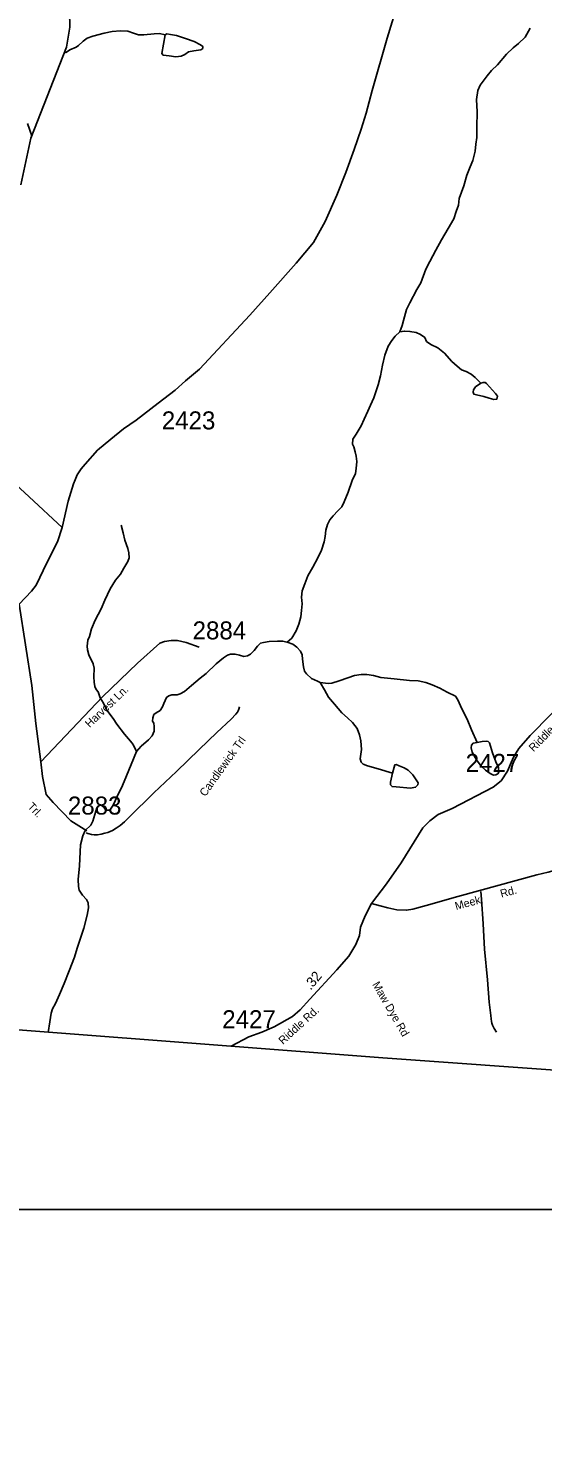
# Model space of a CAD drawing. Extents: x 1268485 to 1426702, y 514839 to 616766.
# Drawn here: x 1353261 to 1357479, y 515585 to 527189 of the extents above; entities that cross this region are included whole.
import ezdxf

# ---------------------------------------------------------------- set-up
doc = ezdxf.new("R2010")
doc.units = 0
for name, color, linetype in [('Old_Level_10', 7, 'Continuous'), ('Old_Level_11', 7, 'Continuous'), ('Old_Level_17', 7, 'Continuous'), ('Old_Level_32', 7, 'Continuous'), ('Old_Level_35', 7, 'Continuous'), ('Old_Level_52', 7, 'Continuous'), ('Old_Level_59', 7, 'Continuous'), ('Old_Level_62', 7, 'Continuous'), ('Old_Level_63', 7, 'Continuous'), ('Old_Level_8', 7, 'Continuous')]:
    doc.layers.add(name, color=color, linetype=linetype)

msp = doc.modelspace()

# ---------------------------------------------------------------- linework, layer by layer
at = {"layer": 'Old_Level_32'}
for points in [[(1356274.314, 527339.472), (1356204.23, 527108.832), (1356081.106, 526678.797), (1356031.384, 526491.805), (1355991.606, 526362.243), (1355934.307, 526193.629), (1355864.222, 526005.258), (1355791.296, 525820.563), (1355696.586, 525604.627), (1355600.455, 525433.257), (1355458.391, 525264.183), (1355242.453, 525019.761), (1355077.659, 524837.823), (1354665.299, 524394.975), (1354551.123, 524299.427), (1354465.311, 524221.316), (1354326.896, 524114.449), (1354145.716, 523974.995), (1354040.114, 523905.619), (1353937.828, 523821.082), (1353827.965, 523729.194), (1353727.099, 523615.713), (1353694.898, 523577.12), (1353661.749, 523528.419), (1353645.649, 523487.07), (1353630.495, 523453.99), (1353588.803, 523312.114), (1353537.161, 523096.675)], [(1353537.161, 523096.675), (1353266.596, 523346.181), (1352892.233, 523690.602), (1352735.016, 523837.622)], [(1353537.161, 523096.675), (1353500.054, 522977.251), (1353413.978, 522807.132), (1353324.923, 522623.315), (1353287.817, 522575.04), (1353184.651, 522468.203)], [(1353184.651, 522468.203), (1353289.673, 521801.897), (1353321.213, 521489.966), (1353363.462, 521174.024)], [(1353363.462, 521174.024), (1353869.457, 521708.317), (1354157.031, 521983.113), (1354340.706, 522146.506), (1354377.813, 522161.36), (1354431.617, 522168.786), (1354483.565, 522170.643), (1354554.067, 522153.933), (1354661.675, 522114.941)], [(1358031.866, 522051.038), (1357906.61, 521921.461), (1357804.568, 521817.484), (1357715.513, 521735.787), (1357377.847, 521390.435), (1357283.226, 521284.601), (1357238.698, 521212.189), (1357220.145, 521169.484), (1357191.799, 521097.247), (1357138.763, 521018.224), (1357072.466, 520966.767), (1356736.249, 520793.099), (1356622.597, 520743.48), (1356554.407, 520690.185), (1356497.582, 520633.215), (1356318.581, 520347.445), (1356197.354, 520174.697), (1356076.128, 520012.984)], [(1353363.462, 521174.024), (1353376.872, 521054.377), (1353408.412, 520905.838), (1353464.64, 520841.132), (1353608.786, 520691.2), (1353740.513, 520609.504)], [(1356076.128, 520012.984), (1356146.212, 519994.607), (1356209.667, 519978.986), (1356283.215, 519960.383), (1356362.993, 519958.527), (1356414.942, 519967.81), (1356524.101, 519997.364), (1356783.603, 520070.873), (1357431.412, 520247.297), (1357524.227, 520271.187), (1357584.84, 520285.889), (1357620.893, 520289.021), (1357672.841, 520279.737), (1357694.703, 520269.35), (1357880.999, 520210.952), (1358175.63, 520142.339), (1358218.443, 520123.248), (1358294.211, 520080.981), (1358392.708, 520018.497), (1358745.971, 519782.347)], [(1356076.128, 520012.984), (1356023.091, 519911.908), (1355985.207, 519818.182), (1355977.857, 519750.186), (1355947.63, 519677.802), (1355890.631, 519583.044), (1355792.177, 519470.772), (1355570.379, 519228.093), (1355489.475, 519141.881), (1355427.295, 519087.321), (1355276.591, 519003.549), (1355177.274, 518959.611), (1355070.598, 518919.777), (1354923.757, 518842.565)]]:
    msp.add_lwpolyline(points, dxfattribs=at)
at = {"layer": 'Old_Level_35'}
for points in [[(1353736.339, 520593.878), (1353748.421, 520588.178), (1353759.801, 520584.231), (1353779.589, 520579.565), (1353802.144, 520576.9), (1353827.981, 520577.567), (1353857.201, 520581.565), (1353887.139, 520588.844), (1353913.59, 520596.79), (1353950.705, 520612.733), (1353981.975, 520630.008), (1354013.861, 520651.898), (1354049.642, 520682.399), (1354082.861, 520716.233), (1354147.862, 520781.286), (1354230.088, 520860.231), (1354291.296, 520919.952), (1354476.971, 521096.502), (1354662.851, 521276.332), (1354808.13, 521414.333), (1354923.574, 521525.163), (1354962.124, 521564.995), (1354975.35, 521580.886), (1354982.629, 521592.164), (1354987.961, 521605.441), (1354991.959, 521625.331)], [(1356972.147, 520113.226), (1356977.273, 520049.711), (1356990.294, 519846.864), (1357002.495, 519640.171), (1357025.871, 519386.829), (1357041.147, 519204.794), (1357053.04, 519096.014), (1357056.629, 519068.947), (1357059.397, 519045.981), (1357062.78, 519032.448), (1357068.111, 519016.915), (1357081.03, 518989.182), (1357099.895, 518958.116)]]:
    msp.add_lwpolyline(points, dxfattribs=at)
at = {"layer": 'Old_Level_52'}
msp.add_lwpolyline([(1390386.565, 515584.903), (1384780.066, 516073.469), (1382090.885, 516373.285), (1380837.056, 516499.357), (1377653.026, 516857.552), (1375435.218, 517115.671), (1374243.431, 517242.496), (1370986.027, 517544.143), (1365028.634, 518085.998), (1364947.704, 518099.982), (1362624.375, 518268.785), (1357811.876, 518630.949), (1356167.665, 518747.074), (1351928.686, 519072.487), (1346107.779, 519526.78), (1342010.801, 519849.137), (1339673.829, 520032.629), (1338463.06, 520121.224), (1334735.72, 520417.336), (1328377.203, 520903.463), (1327643.106, 520964.699), (1325231.308, 521115.741), (1322642.809, 521300.009)], dxfattribs=at)
at = {"layer": 'Old_Level_59'}
msp.add_lwpolyline([(1353198.266, 525906.153), (1353281.21, 526288.575), (1353573.204, 527034.4), (1353602.219, 527197.878), (1353594.222, 527591.988), (1353490.158, 527794.272), (1353453.834, 528034.451), (1353520.17, 528153.941), (1353543.164, 528324.998), (1353479.187, 528444.441), (1353408.137, 529020.329), (1353254.143, 529207.234)], dxfattribs=at)
at = {"layer": 'Old_Level_62'}
for points in [[(1353564.988, 526988.108), (1353600.373, 527011.639), (1353652.969, 527034.4), (1353673.167, 527046.293), (1353711.922, 527083.254), (1353742.474, 527106.425), (1353790.969, 527123.495), (1353883.55, 527149.537), (1353947.834, 527162.199), (1354015.911, 527166.608), (1354075.991, 527163.737), (1354123.666, 527147.999), (1354165.394, 527135.696), (1354207.43, 527134.825), (1354293.654, 527144.565), (1354337.638, 527145.333), (1354383.57, 527134.568)], [(1356306.856, 524698.857), (1356328.079, 524752.58), (1356338.844, 524792.566), (1356362.937, 524884.019), (1356390.107, 524937.64), (1356446.496, 525046.472), (1356479.817, 525103.219), (1356522.263, 525214.768), (1356553.636, 525275.72), (1356603.771, 525370.71), (1356649.6, 525454.32), (1356703.734, 525548.388), (1356751.409, 525625.385), (1356770.786, 525685.722), (1356787.908, 525738.728), (1356795.187, 525792.759), (1356831.481, 525897.899), (1356857.42, 525983.508), (1356884.897, 526052.713), (1356906.12, 526104.796), (1356925.805, 526182.358), (1356931.034, 526238.08), (1356940.262, 526293.701), (1356938.108, 526378.285), (1356940.877, 526503.777), (1356937.083, 526603.945), (1356946.618, 526678.43), (1356965.688, 526721.542), (1357025.358, 526798.283), (1357060.32, 526843.548), (1357107.379, 526888.557), (1357181.403, 526977.345), (1357238.51, 527027.89), (1357281.366, 527064.748), (1357334.474, 527115.396), (1357376.202, 527190.855)], [(1354383.57, 527134.568), (1354356.093, 526983.291), (1354365.833, 526969.143), (1354415.66, 526961.607), (1354471.537, 526954.737), (1354513.675, 526959.608), (1354544.023, 526972.987), (1354574.473, 526996.158), (1354618.764, 527005.129), (1354674.949, 527012.204), (1354691.148, 527024.147), (1354691.455, 527039.731), (1354673.821, 527052.394), (1354620.405, 527079.768), (1354550.892, 527104.938), (1354477.381, 527130.211), (1354427.553, 527137.798), (1354395.668, 527142.514), (1354383.57, 527134.568)], [(1353288.714, 526307.741), (1353254.963, 526408.889)], [(1355382.378, 522156.313), (1355421.133, 522189.173), (1355458.453, 522248.331), (1355479.676, 522303.695), (1355497.002, 522363.263), (1355502.129, 522415.704), (1355507.358, 522471.376), (1355500.488, 522524.024), (1355507.665, 522575.594), (1355528.991, 522633.419), (1355552.366, 522700.266), (1355593.992, 522769.984), (1355635.823, 522848.724), (1355665.145, 522910.495), (1355686.676, 522979.854), (1355695.595, 523021.531), (1355700.722, 523073.922), (1355715.793, 523119.597), (1355732.607, 523158.608), (1355761.417, 523192.493), (1355800.274, 523233.606), (1355831.135, 523266.62), (1355851.845, 523306.4), (1355883.731, 523385.345), (1355915.821, 523480.745), (1355943.196, 523540.057), (1355949.962, 523578.504), (1355955.294, 523638.327), (1355950.168, 523680.261), (1355940.94, 523716.555), (1355929.867, 523757.002), (1355920.435, 523779.352), (1355923.306, 523821.131), (1355950.168, 523862.449), (1355991.691, 523929.706), (1356014.861, 523985.07), (1356044.389, 524048.483), (1356067.457, 524098.054), (1356094.832, 524159.057), (1356129.178, 524265.018), (1356148.76, 524338.529), (1356166.805, 524425.932), (1356184.542, 524509.286), (1356212.224, 524583.412), (1356243.289, 524630.369), (1356270.049, 524665.946), (1356306.856, 524698.857)], [(1356306.856, 524698.857), (1356344.995, 524706.29), (1356390.927, 524702.907), (1356440.857, 524694.5), (1356476.331, 524677.378), (1356513.958, 524652.823), (1356527.287, 524622.219), (1356562.658, 524595.255), (1356620.073, 524570.289), (1356673.181, 524526.562), (1356733.672, 524457.203), (1356778.886, 524418.551), (1356814.257, 524389.946), (1356851.987, 524375.234), (1356891.562, 524353.908), (1356924.883, 524325.354), (1356971.942, 524280.09)], [(1356971.942, 524280.09), (1356929.189, 524248.922), (1356912.682, 524225.494), (1356910.324, 524205.809), (1356913.912, 524189.354), (1356937.698, 524183.1), (1356997.471, 524169.617), (1357039.302, 524156.443), (1357078.979, 524144.191), (1357103.073, 524146.959), (1357107.584, 524171.514), (1357092.205, 524195.608), (1357043.3, 524248.306), (1357017.874, 524277.526), (1357008.031, 524285.113), (1356990.089, 524285.472), (1356971.942, 524280.09)], [(1354148.067, 521260.441), (1354127.049, 521305.142), (1354113.516, 521327.595), (1354082.246, 521364.351), (1354049.027, 521401.107), (1353986.794, 521482.769), (1353955.831, 521529.367), (1353905.286, 521598.469), (1353876.578, 521654.859), (1353849.511, 521699.714), (1353832.697, 521750.105), (1353817.011, 521768.457), (1353807.578, 521792.449), (1353800.401, 521828.743), (1353799.274, 521870.573), (1353800.914, 521942.803), (1353791.687, 521979.046), (1353757.238, 522051.994), (1353746.165, 522094.029), (1353742.884, 522124.48), (1353748.011, 522173.64), (1353762.672, 522203.68), (1353777.948, 522265.76), (1353809.526, 522336.503), (1353857.611, 522429.905), (1353889.189, 522499.007), (1353933.275, 522592.511), (1353974.901, 522663.049), (1354016.014, 522712.312), (1354045.029, 522761.781), (1354078.247, 522816.889), (1354086.859, 522847.083), (1354085.834, 522887.324), (1354076.607, 522922.798), (1354052.103, 522991.388), (1354039.39, 523052.391), (1354022.883, 523114.266)], [(1354148.067, 521260.441), (1354187.027, 521303.964), (1354246.185, 521354.457), (1354276.943, 521388.291), (1354291.809, 521427.405), (1354292.629, 521463.494), (1354289.143, 521491.484), (1354279.506, 521508.093), (1354282.171, 521535.928), (1354290.784, 521562.022), (1354309.136, 521577.246), (1354341.534, 521594.625), (1354360.194, 521624.613), (1354372.804, 521653.885), (1354393.925, 521703.558), (1354412.277, 521717.092), (1354436.473, 521724.833), (1354482.405, 521725.551), (1354506.703, 521733.291), (1354541.05, 521750.618), (1354598.157, 521801.163), (1354669.515, 521861.295), (1354718.42, 521898.871), (1354802.183, 521978.431), (1354861.238, 522027.285), (1354893.739, 522048.815), (1354917.935, 522056.505), (1354957.92, 522057.376), (1354993.805, 522048.456), (1355029.586, 522039.485), (1355059.729, 522043.022), (1355084.028, 522058.914), (1355112.735, 522087.878), (1355139.494, 522123.454), (1355164.1, 522146.779), (1355190.245, 522154.417), (1355236.381, 522160.876), (1355304.561, 522163.644), (1355346.494, 522164.413), (1355382.378, 522156.313)], [(1355382.378, 522156.313), (1355429.95, 522138.936), (1355463.476, 522114.483), (1355492.901, 522083.52), (1355506.23, 522052.916), (1355509.408, 522017.545), (1355517.918, 521952.543), (1355525.3, 521918.761), (1355542.729, 521896.257), (1355583.945, 521857.655), (1355631.517, 521836.176), (1355653.252, 521825.924)], [(1355653.252, 521825.924), (1355721.022, 521816.337), (1355751.164, 521819.823), (1355811.552, 521838.329), (1355882.295, 521864.781), (1355934.584, 521883.441), (1355990.768, 521892.156), (1356036.802, 521891.233), (1356090.731, 521881.954), (1356152.349, 521865.089), (1356262.154, 521854.682), (1356387.954, 521841.508), (1356457.979, 521838.432), (1356521.75, 521824.847), (1356573.218, 521805.777), (1356634.734, 521778.249), (1356696.044, 521745.031), (1356763.404, 521713.298), (1356784.627, 521683.31), (1356815.077, 521610.516), (1356859.163, 521525.112), (1356895.253, 521438.221), (1356941.082, 521333.081)], [(1355653.252, 521825.924), (1355689.956, 521765.279), (1355722.662, 521706.327), (1355771.362, 521647.118), (1355831.852, 521577.759), (1355879.014, 521536.595), (1355920.23, 521498.045), (1355957.037, 521447.243), (1355977.952, 521396.75), (1355988.82, 521346.46), (1355993.228, 521275.82), (1355983.694, 521200.515), (1355990.973, 521172.474), (1356006.659, 521155.762), (1356042.338, 521142.69), (1356129.896, 521118.802), (1356247.185, 521082.815)], [(1353422.436, 518956.352), (1353436.947, 519043.469), (1353448.532, 519114.623), (1353459.297, 519150.558), (1353484.211, 519194.336), (1353517.84, 519267.54), (1353553.929, 519357.045), (1353596.272, 519462.083), (1353640.563, 519572.76), (1353660.248, 519646.22), (1353716.023, 519811.697), (1353742.269, 519917.042), (1353753.547, 519976.712), (1353752.522, 520018.595), (1353739.091, 520046.738), (1353705.872, 520081.904), (1353676.755, 520122.709), (1353673.372, 520152.289), (1353670.706, 520210.626), (1353679.216, 520322.892), (1353688.956, 520494.161), (1353706.59, 520567.672), (1353727.608, 520611.554), (1353774.565, 520656.563), (1353789.226, 520688.295), (1353806.451, 520742.121), (1353823.675, 520797.588), (1353840.182, 520816.913), (1353858.124, 520819.015), (1353879.859, 520802.201), (1353895.238, 520778.056), (1353913.283, 520777.697), (1353929.379, 520779.03), (1353956.241, 520820.348), (1353989.87, 520890.219), (1354033.853, 520981.263), (1354065.534, 521060.208), (1354103.674, 521153.814), (1354148.067, 521260.441)], [(1356941.082, 521333.081), (1356908.991, 521327.955), (1356896.585, 521312.627), (1356892.074, 521290.533), (1356901.302, 521254.289), (1356935.853, 521191.185), (1356974.813, 521138.743), (1357010.082, 521105.986), (1357049.452, 521078.97), (1357077.236, 521066.103), (1357095.281, 521068.205), (1357111.48, 521077.689), (1357119.785, 521091.478), (1357116.606, 521127.67), (1357095.691, 521175.704), (1357067.291, 521248.445), (1357042.993, 521329.39), (1357033.253, 521341.078), (1357021.257, 521343.744), (1356983.117, 521340.411), (1356941.082, 521333.081)], [(1356247.185, 521082.815), (1356231.499, 521008.432), (1356231.089, 520987.106), (1356244.725, 520972.035), (1356278.763, 520969.729), (1356396.566, 520959.169), (1356436.756, 520966.55), (1356455.211, 520987.517), (1356457.569, 521003.87), (1356436.243, 521036.319), (1356415.021, 521068.769), (1356375.753, 521105.627), (1356342.125, 521124.389), (1356302.447, 521141.562), (1356276.713, 521151.968), (1356266.665, 521149.713), (1356262.257, 521130.079), (1356247.185, 521082.815)]]:
    msp.add_lwpolyline(points, dxfattribs=at)
at = {"layer": 'Old_Level_63'}
msp.add_lwpolyline([(1305516.95, 529802.059), (1368033.021, 529802.059), (1368033.021, 517504.204), (1305516.95, 517504.204), (1305516.95, 529802.059)], dxfattribs=at)

# ---------------------------------------------------------------- texts
at = {"layer": 'Old_Level_10'}
for s, height, rotation, p in [('Candlewick Trl', 65.61666, 54.364425, (1354712.567, 520885.406)), ('Maw Dye Rd', 65.6167, 300.0582444, (1356079.602, 519350.119))]:
    msp.add_text(s, height=height, rotation=rotation, dxfattribs=at).set_placement(p)
at = {"layer": 'Old_Level_11'}
for s, height, rotation, p in [('Harvest Ln.', 65.61666, 43.6984472, (1353764.173, 521450.733)), ('Riddle Rd.', 65.6167, 45.6446667, (1357405.137, 521253.107)), ('Trl.', 65.6167, 313.8727389, (1353249.675, 520803.505)), ('Meek       Rd.', 65.61666, 15.2344056, (1356769.397, 519959.221)), ('Riddle Rd.', 65.6167, 42.4206333, (1355349.138, 518853.467))]:
    msp.add_text(s, height=height, rotation=rotation, dxfattribs=at).set_placement(p)
at = {"layer": 'Old_Level_17'}
msp.add_text('.32', height=82.0208, rotation=50.4062472, dxfattribs=at).set_placement((1355576.301, 519298.166))
at = {"layer": 'Old_Level_8'}
for s, p in [('2423', (1354355.675, 523900.314)), ('2884', (1354608.309, 522178.603)), ('2427', (1356847.711, 521092.481)), ('2883', (1353585.583, 520742.464)), ('2427', (1354851.185, 518991.053))]:
    msp.add_text(s, height=147.6375, dxfattribs=at).set_placement(p)

doc.saveas('drawing.dxf')
